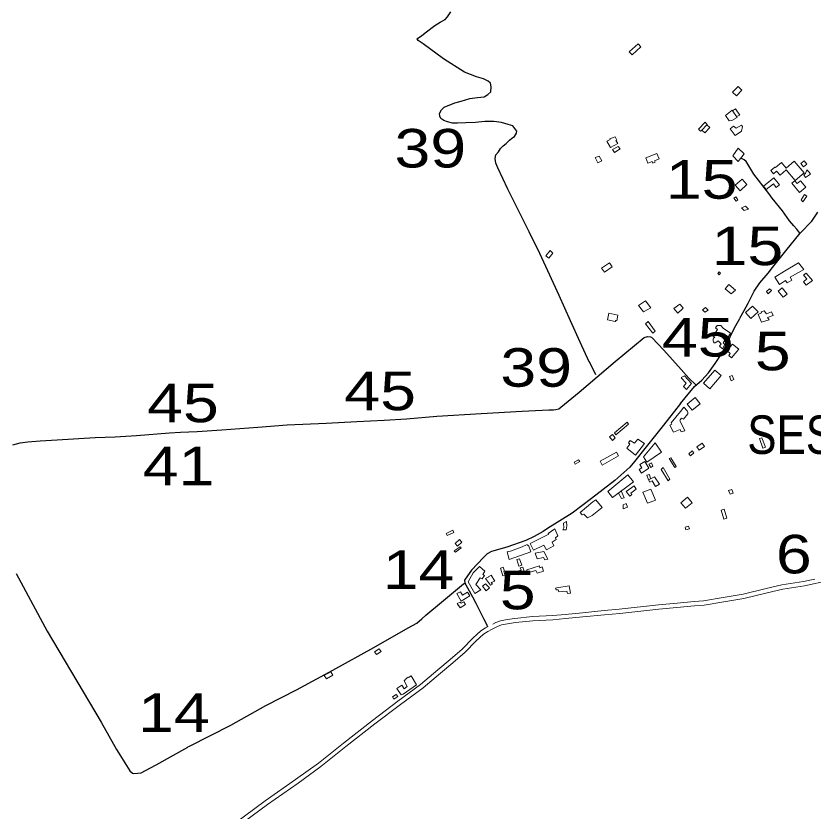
# Model space of a CAD drawing. Extents: x 476989 to 498418, y 4381813 to 4416555.
# Drawn here: x 484565 to 485599, y 4384627 to 4385658 of the extents above; entities that cross this region are included whole.
import ezdxf
from ezdxf.enums import TextEntityAlignment as Align

# ---------------------------------------------------------------- set-up
doc = ezdxf.new("R2010")
doc.units = 0
doc.header["$LTSCALE"] = 20
doc.linetypes.add('MEDIUM_DASHED', pattern=[4.5, 3, -1.5])
for name, color, linetype, lineweight in [('13', 7, 'Continuous', 13), ('36', 7, 'Continuous', 13), ('47', 7, 'Continuous', 13), ('48', 7, 'MEDIUM_DASHED', 13), ('6', 7, 'Continuous', 25)]:
    doc.layers.add(name, color=color, linetype=linetype, lineweight=lineweight)
doc.layers.add('7', color=7, linetype='Continuous')

msp = doc.modelspace()

# ---------------------------------------------------------------- linework, layer by layer
at = {"layer": '36'}
for points in [[(485422.69, 4384896.4), (485445.04, 4384898.28), (485457.06, 4384899.22), (485464.89, 4384900.34), (485474.69, 4384902.21), (485508.34, 4384907.79), (485538.44, 4384915.04), (485558.81, 4384919.82), (485586.93, 4384924.38), (485601.44, 4384927.38)], [(485422.62, 4384890.78), (485445.5, 4384892.7), (485457.67, 4384893.65), (485465.81, 4384894.8), (485475.68, 4384896.69), (485509.45, 4384902.29), (485539.74, 4384909.58), (485559.9, 4384914.32), (485587.94, 4384918.87), (485619.65, 4384925.47)], [(485183.89, 4384869.09), (485187.49, 4384870.96), (485193.57, 4384873.46), (485202.11, 4384874.97), (485212.4, 4384876.37), (485235.13, 4384878.7), (485261.36, 4384880.1), (485277.67, 4384881.57), (485300.11, 4384883.76), (485328.15, 4384886.54), (485347.71, 4384888.4), (485398.68, 4384894.02), (485422.69, 4384896.4)], [(484851.61, 4384605.75), (484891.48, 4384635.27), (484931.04, 4384662.95), (484960.7, 4384684.23), (484993.21, 4384710.28), (485030.75, 4384739.64), (485063.92, 4384764.85), (485093.47, 4384786.49), (485116.03, 4384805.54), (485131.93, 4384818.81), (485147.77, 4384832.69), (485161.73, 4384847.04), (485171.53, 4384855.86), (485177.07, 4384859.62), (485182.06, 4384861.97), (485189.79, 4384866.01), (485195.1, 4384868.19), (485202.95, 4384869.58), (485213.04, 4384870.95), (485235.55, 4384873.26), (485261.75, 4384874.66), (485278.18, 4384876.14), (485300.64, 4384878.33), (485328.67, 4384881.11), (485348.27, 4384882.97), (485399.25, 4384888.59), (485422.62, 4384890.78)], [(484707.31, 4384502.21), (484734.52, 4384522.99), (484765.58, 4384547.94), (484791.08, 4384567.66), (484812.71, 4384583.16), (484848.35, 4384610.12), (484888.3, 4384639.7), (484927.89, 4384667.41), (484957.41, 4384688.58), (484989.83, 4384714.56), (485027.43, 4384743.96), (485060.66, 4384769.23), (485090.09, 4384790.79), (485112.52, 4384809.73), (485128.38, 4384822.96), (485144.01, 4384836.66), (485157.94, 4384850.98), (485168.16, 4384860.16), (485174.35, 4384864.37), (485176.85, 4384865.55)]]:
    msp.add_lwpolyline(points, dxfattribs=at)
at = {"layer": '47'}
for p, q in [((485429.64, 4385279.89), (485430.73, 4385278.66)), ((485430.73, 4385278.66), (485429.6, 4385277.65)), ((485431.59, 4385150.48), (485427.01, 4385144.68))]:
    msp.add_line(p, q, dxfattribs=at)
for points in [[(485375.86, 4385617.36), (485364.42, 4385607.2), (485360.77, 4385611.28), (485372.16, 4385621.45)], [(485501.94, 4385566.31), (485494.71, 4385558.99), (485499.66, 4385554.11), (485506.89, 4385561.43)], [(485500.76, 4385525.8), (485493.57, 4385522.16), (485490.11, 4385521.53), (485485.71, 4385528.5), (485494.07, 4385535.43)], [(485461.45, 4385516.54), (485454.91, 4385509.66), (485458.68, 4385506.07), (485465.22, 4385512.95)], [(485491.39, 4385511.08), (485498.17, 4385502.8), (485506.43, 4385508.01), (485507.49, 4385514.15), (485506.17, 4385515.97), (485499.43, 4385512.02), (485496.02, 4385514.62)], [(485336.5, 4385486.96), (485331.77, 4385495.38), (485335.76, 4385497.44), (485335.29, 4385498.25), (485342.2, 4385500.73), (485344.58, 4385496.66), (485343.21, 4385496.15), (485345.76, 4385492.09)], [(485346.38, 4385488.49), (485348.86, 4385485.12), (485341.52, 4385480.52), (485338.96, 4385484.25)], [(485501.99, 4385486.17), (485494.94, 4385476.06), (485501.89, 4385468.84), (485509.91, 4385478.63)], [(485316.66, 4385474.25), (485319.79, 4385467.3), (485324.91, 4385469.72), (485321.65, 4385475.92)], [(485382.2, 4385473.84), (485385, 4385466.76), (485390.55, 4385468.79), (485391.34, 4385466.68), (485394.27, 4385468.09), (485393.65, 4385469.76), (485399.3, 4385472.35), (485396.43, 4385479.26)], [(485576.12, 4385444.28), (485564.24, 4385457.89), (485556.57, 4385451.2), (485551.89, 4385456.56), (485547.94, 4385453.11), (485544.46, 4385457.09), (485549.66, 4385461.64), (485550.29, 4385460.91), (485558.02, 4385467.59), (485564.31, 4385460.3), (485574.72, 4385469.29), (485587.69, 4385454.27)], [(485583.19, 4385466.47), (485586.58, 4385462.08), (485591.06, 4385465.53), (485587.67, 4385469.92)], [(485591.25, 4385458.17), (485589.16, 4385453.18), (485586.96, 4385451.48), (485589.53, 4385448.14), (485595.75, 4385452.26), (485594.06, 4385455.21)], [(485513.39, 4385438.88), (485504.37, 4385430.87), (485498, 4385438.05), (485507.02, 4385446.06)], [(485534.82, 4385436.85), (485548.41, 4385447.53), (485555.55, 4385438.42), (485551.49, 4385435.24), (485547.76, 4385439.99), (485538.35, 4385432.6)], [(485571.57, 4385440.75), (485581.68, 4385428.75), (485589.75, 4385435.55), (485582.63, 4385443.99), (485578.45, 4385440.47), (485575.5, 4385443.96)], [(485488.51, 4385430.38), (485490.9, 4385426.94), (485494.12, 4385429.18), (485491.73, 4385432.62)], [(485587.94, 4385426.11), (485583.51, 4385419.27), (485585.96, 4385416.4), (485590.99, 4385424.11)], [(485496.41, 4385421.49), (485499.18, 4385417.58), (485501.63, 4385419.31), (485498.86, 4385423.22)], [(485515.18, 4385406.96), (485509.98, 4385405.16), (485506.28, 4385408.67), (485511.49, 4385410.99)], [(485261.75, 4385350.07), (485256.55, 4385343.42), (485252.49, 4385346.53), (485257.99, 4385353.63)], [(485328.63, 4385325.22), (485324.86, 4385330.61), (485335.14, 4385337.31), (485338.56, 4385332.44)], [(485549.71, 4385318.83), (485561.98, 4385326.75), (485580.37, 4385337.6), (485587.23, 4385328.94), (485569.52, 4385318.84), (485571.72, 4385315.06), (485565.44, 4385311.55), (485563.46, 4385314.43), (485555.65, 4385309.29)], [(485477.4, 4385325.79), (485479.27, 4385324.15), (485477.42, 4385322.04), (485475.55, 4385323.68)], [(485590.08, 4385308.34), (485598.5, 4385314.38), (485590.16, 4385324.25), (485586.82, 4385321.45), (485590.88, 4385316.59), (485586.69, 4385312.74)], [(485498.45, 4385302.23), (485490, 4385309.55), (485485.17, 4385303.97), (485492.83, 4385297.33)], [(485542.75, 4385303.99), (485538.6, 4385300.17), (485540.85, 4385297.49), (485545.11, 4385301.63)], [(485559.04, 4385304.89), (485565.52, 4385297.05), (485560.45, 4385292.86), (485553.97, 4385300.7)], [(485379.07, 4385273.78), (485372.7, 4385282.19), (485381.81, 4385288.09), (485388.5, 4385279.35)], [(485462.96, 4385275.95), (485458.57, 4385273.46), (485455.91, 4385276.72), (485459.56, 4385279.6)], [(485520.66, 4385281.5), (485511.38, 4385272.95), (485518.48, 4385265.25), (485527.76, 4385273.8)], [(485345.88, 4385269.62), (485344.44, 4385262.34), (485343.13, 4385262.81), (485342.47, 4385261.32), (485332.59, 4385263.42), (485334.26, 4385272.11)], [(485535.88, 4385275.28), (485538.53, 4385271.26), (485545.24, 4385273.79), (485547.35, 4385269.41), (485540.18, 4385266.44), (485542.09, 4385263.63), (485532.37, 4385260.7), (485528.09, 4385270.51), (485532.09, 4385272.56), (485531.74, 4385273.91)], [(485385.42, 4385261.39), (485394.28, 4385248.91), (485391.08, 4385246.45), (485381.82, 4385258.29)], [(485491.87, 4385246.19), (485482.36, 4385252.63), (485479.41, 4385256.13), (485474.53, 4385256.42), (485472.69, 4385253.22), (485475.36, 4385251.23), (485469.68, 4385242.53), (485471.61, 4385240.93), (485470.02, 4385239.75), (485469.7, 4385238.63), (485469.68, 4385237.51), (485469.66, 4385235.93), (485469.95, 4385235.1), (485470.91, 4385233.81), (485472.33, 4385233.94), (485474.23, 4385235.19), (485476.05, 4385236.29), (485479.89, 4385232.48), (485477.67, 4385229.44), (485481.67, 4385225.85), (485484.68, 4385231.74), (485482.54, 4385233.72), (485485.91, 4385239.08), (485487.71, 4385238.75)], [(485502.9, 4385225.4), (485493.14, 4385214.36), (485489.67, 4385217.42), (485491.81, 4385219.85), (485487.35, 4385223.77), (485494.77, 4385232.21)], [(485471.75, 4385198.38), (485457.07, 4385181.29), (485465.18, 4385174.32), (485479.86, 4385191.41)], [(485494.31, 4385191.46), (485496.54, 4385186.14), (485492.79, 4385184.57), (485490.56, 4385189.89)], [(485446.33, 4385162.95), (485435.67, 4385154.43), (485442.19, 4385146.28), (485452.85, 4385154.8)], [(485341.54, 4385117.13), (485358, 4385131.01), (485359.88, 4385128.25), (485343.44, 4385114.36)], [(485335.12, 4385111.93), (485338.88, 4385107.2), (485342.55, 4385110.64), (485339.07, 4385115.06)], [(485357.51, 4385097.15), (485368.62, 4385088.17), (485380.36, 4385103.26), (485372.01, 4385109.03), (485367.56, 4385103.58), (485362.09, 4385107.01), (485359.66, 4385104.07), (485361.62, 4385102.4)], [(485379.23, 4385085.92), (485383.64, 4385079.14), (485402.54, 4385092.1), (485394.26, 4385104.11)], [(485458.4, 4385099.53), (485451.27, 4385094.65), (485448.34, 4385098.92), (485455.47, 4385103.8)], [(485532.7, 4385110.77), (485537.34, 4385098.3), (485534.08, 4385097.09), (485529.44, 4385109.56)], [(485444.62, 4385090.94), (485440.26, 4385087.1), (485437.78, 4385089.92), (485442.14, 4385093.76)], [(485346.7, 4385087.36), (485344.04, 4385092.2), (485323.12, 4385080.13), (485325.71, 4385075.16)], [(485414.69, 4385084.77), (485421.67, 4385073.34), (485420.02, 4385071.95), (485412.62, 4385083.7)], [(485290.74, 4385076.25), (485296.71, 4385079.76), (485295.04, 4385081.98), (485289.22, 4385078.94)], [(485376.42, 4385064.78), (485386.3, 4385071.05), (485380.99, 4385079.78), (485374.59, 4385076.18), (485377.22, 4385071.74), (485373.36, 4385069.71)], [(485386.27, 4385076.22), (485388.49, 4385071.93), (485391.18, 4385073.68), (485389.36, 4385078.3)], [(485401.88, 4385069.6), (485410.97, 4385054.66), (485413.3, 4385056.85), (485404.78, 4385072.14)], [(485332.83, 4385040.86), (485358.81, 4385062.46), (485366.1, 4385053.67), (485338.95, 4385033.1)], [(485400.09, 4385050.6), (485393.57, 4385059.83), (485385.55, 4385056.3), (485387.34, 4385053.1), (485390.5, 4385054.62), (485394.78, 4385047.66)], [(485356.66, 4385040.89), (485366.9, 4385048.44), (485369.63, 4385044), (485362.81, 4385039.04), (485363.91, 4385036.96), (485361.23, 4385035.02)], [(485378.19, 4385039.92), (485388.72, 4385044.18), (485394.8, 4385029.82), (485384.25, 4385025.7)], [(485489.62, 4385042.13), (485493.73, 4385043.77), (485495.65, 4385038.96), (485491.54, 4385037.32)], [(485436.15, 4385033.44), (485427.79, 4385026.2), (485433.84, 4385019.21), (485442.2, 4385026.45)], [(485317.22, 4385029.98), (485325.37, 4385020.45), (485312.51, 4385010.01), (485306.62, 4385006.83), (485301.81, 4385011.58), (485299.61, 4385010.55), (485296.92, 4385013.86), (485313.3, 4385027.75)], [(485356.54, 4385025.58), (485358.36, 4385020.59), (485352.67, 4385018.3), (485352.65, 4385023.86)], [(485483.95, 4385017.97), (485487.31, 4385006.49), (485483.24, 4385005.3), (485479.88, 4385016.78)], [(485275.35, 4384999.72), (485275.62, 4384993.72), (485274.51, 4384991.12), (485278.93, 4384991.49), (485279.63, 4384996.44), (485279.21, 4385002.07)], [(485131.88, 4384990.73), (485133.04, 4384987.96), (485124.38, 4384983.93), (485123.04, 4384986.67)], [(485232.24, 4384973.73), (485256.24, 4384985.71), (485255.64, 4384986.42), (485264.26, 4384992.64), (485267.98, 4384983.55), (485264.85, 4384980.92), (485265.96, 4384978.66), (485260.82, 4384975.22), (485262.98, 4384970.42), (485253.45, 4384965.37), (485249.92, 4384971.55), (485236.63, 4384965.07)], [(485434.27, 4384991.29), (485438.67, 4384992.73), (485437.56, 4384996.12), (485433.16, 4384994.68)], [(485135.13, 4384962.27), (485133.6, 4384964.2), (485141.49, 4384969.44), (485142.72, 4384967.81)], [(485134.96, 4384973.48), (485137.8, 4384970.26), (485143.62, 4384975.18), (485140.65, 4384978.64)], [(485202.26, 4384962.64), (485205.11, 4384952.88), (485232.87, 4384962.57), (485229.87, 4384971.23), (485228.85, 4384971.04), (485228.23, 4384972.06), (485221.76, 4384969.24), (485206.44, 4384963.71)], [(485241.19, 4384953.59), (485238.74, 4384961.16), (485249.91, 4384963.4), (485255.04, 4384953.22), (485251.01, 4384952.26), (485249.57, 4384955.39)], [(485218.26, 4384953.88), (485221.3, 4384945.37), (485217.52, 4384944.38), (485214.88, 4384952.63)], [(485166.54, 4384943.66), (485173.38, 4384937.5), (485170.74, 4384933.52), (485172.96, 4384932.16), (485170.02, 4384927.89), (485167.44, 4384928.93), (485161.73, 4384920.25), (485168.12, 4384913.52), (485160.35, 4384908.85), (485151.84, 4384923.7), (485158.04, 4384935.36)], [(485196.83, 4384931.59), (485193.55, 4384941.49), (485197.01, 4384942.93), (485198.74, 4384937.86), (485198.11, 4384937.64), (485199.61, 4384932.22)], [(485222.65, 4384942.91), (485225.26, 4384935.23), (485216.88, 4384932.94), (485215.88, 4384937.84), (485220.3, 4384938.94), (485219.08, 4384941.85)], [(485249.49, 4384937.5), (485241.12, 4384935.21), (485239.52, 4384938.69), (485228.76, 4384935.35), (485227.77, 4384939.36), (485244.05, 4384944.48), (485244.89, 4384942.19), (485247.54, 4384943.11)], [(485186.49, 4384924.62), (485181.37, 4384932.42), (485178.47, 4384930.93), (485178.71, 4384930.27), (485174.01, 4384928), (485180.62, 4384919.36), (485183.12, 4384920.9), (485181.75, 4384922.86)], [(485174.13, 4384921.38), (485179.41, 4384916.01), (485175.21, 4384912.35), (485170.29, 4384918.41)], [(485266.7, 4384916.2), (485282.71, 4384918.56), (485284.62, 4384909.24), (485280.59, 4384908.66), (485279.6, 4384911.79), (485269.14, 4384910.81), (485268.41, 4384913.55), (485265.87, 4384913.33), (485264.93, 4384915.83)], [(485142.63, 4384898.78), (485154.08, 4384905.6), (485151.02, 4384910.61), (485144.58, 4384906.61), (485141.69, 4384910.99), (485137.02, 4384908.61)], [(485137.57, 4384895.7), (485141.36, 4384889.94), (485148.18, 4384894.62), (485146.28, 4384897.8), (485142.69, 4384896.02), (485141.37, 4384897.6)], [(485038.74, 4384833.32), (485032.85, 4384829.56), (485030.27, 4384833.1), (485036.4, 4384836.94)], [(484964.87, 4384802.3), (484967.76, 4384797.99), (484976.23, 4384802.68), (484973.49, 4384807.16)], [(485077.7, 4384801.78), (485084.8, 4384790.17), (485067.22, 4384778.07), (485064.7, 4384777.53), (485059.16, 4384785.44), (485065.69, 4384789.96), (485068.86, 4384784.97), (485072.67, 4384788.24), (485068.78, 4384795.47), (485070.08, 4384796.6), (485069.91, 4384797.28), (485073.98, 4384800.36), (485074.47, 4384799.7)], [(485058.21, 4384777.93), (485060.61, 4384775.18), (485055.1, 4384771.73), (485053.37, 4384774.59)]]:
    msp.add_lwpolyline(points, close=True, dxfattribs=at)
for points in [[(485429.64, 4385279.89), (485426.15, 4385283.84), (485418.4, 4385278.2), (485423.65, 4385272.41), (485429.6, 4385277.65)], [(485427.86, 4385188.7), (485432.25, 4385191), (485441.64, 4385181.18)], [(485441.64, 4385181.18), (485434.85, 4385173.17), (485431, 4385177.06), (485434.44, 4385181.58), (485427.86, 4385188.36)], [(485427.01, 4385144.68), (485414.85, 4385130.05), (485416.09, 4385128.19), (485413.43, 4385126.89), (485418.24, 4385117.89), (485426.55, 4385121.28)], [(485426.79, 4385133.81), (485428.39, 4385136.27), (485430.92, 4385134.66), (485436.72, 4385141.78), (485436.75, 4385143.51), (485435.88, 4385145.77), (485431.59, 4385150.48)], [(485426.76, 4385132.14), (485426.34, 4385133.12), (485426.79, 4385133.81)], [(485426.55, 4385121.28), (485428.06, 4385118.42), (485432.65, 4385119.55), (485426.76, 4385132.14)], [(485385.55, 4385056.3), (485383.4, 4385062.17), (485386.75, 4385063.22), (485388.34, 4385057.54)], [(485350.4, 4385041.78), (485353.89, 4385032.82), (485350.82, 4385031.71), (485346.73, 4385039)]]:
    msp.add_lwpolyline(points, dxfattribs=at)
at = {"layer": '48'}
for points in [[(485494.62, 4385534.65), (485498.59, 4385537.17), (485504.3, 4385529.07), (485499.88, 4385527.08)], [(485462.03, 4385516), (485459.32, 4385519.8), (485450.49, 4385510.99), (485453.01, 4385508.33), (485455.17, 4385509.42)]]:
    msp.add_lwpolyline(points, dxfattribs=at)
at = {"layer": '6'}
msp.add_line((485317.14, 4385192.15), (485308.96, 4385209), dxfattribs=at)
for points in [[(485085.26, 4385628.04), (485091.15, 4385632.01), (485096.05, 4385635.71), (485108.29, 4385645.35), (485115.31, 4385649.61), (485121.88, 4385653.16), (485124.79, 4385656.54), (485129.25, 4385663.08)], [(485308.74, 4385209.32), (485296.92, 4385234.62), (485284.43, 4385262.28), (485269.87, 4385294.93), (485255.01, 4385327.15), (485244.49, 4385349.47), (485230.92, 4385377.71), (485215.65, 4385407.92), (485203.16, 4385433.2), (485190.33, 4385460.5), (485187.63, 4385466.91), (485186.62, 4385472.64), (485187.63, 4385477.36), (485190.89, 4385481.57), (485193.57, 4385485.92), (485197.06, 4385489.39), (485200.8, 4385492.38), (485205.32, 4385496.6), (485208.41, 4385498.94), (485211.95, 4385501.28), (485214.31, 4385505.63), (485214.74, 4385508.31), (485209.48, 4385515.04), (485203.51, 4385516.95), (485195.07, 4385519.6), (485184.8, 4385520.86), (485173.16, 4385520.87), (485161.39, 4385519.61), (485148.88, 4385519.03), (485137.95, 4385518.42), (485131.25, 4385518.7), (485124.8, 4385520.19), (485120.08, 4385522.1), (485116.29, 4385524.57), (485114.78, 4385527.83), (485114.56, 4385531.16), (485116.92, 4385535.98), (485120.69, 4385539.39), (485134.43, 4385544.79), (485142.84, 4385547.22), (485153.81, 4385550.55), (485163.77, 4385551.71), (485172.59, 4385552.94), (485177.26, 4385555.7), (485181.21, 4385559.31), (485181.69, 4385565.62), (485180.62, 4385570.61), (485177.49, 4385573.08), (485171.64, 4385576.01), (485162.45, 4385578.88), (485146.78, 4385584.79), (485119.71, 4385602.02), (485093.36, 4385621.51), (485087.04, 4385625.83), (485085.38, 4385628.14)], [(485582.1, 4385375.98), (485578.17, 4385381.31), (485574, 4385385.61), (485568.72, 4385391.95), (485559.52, 4385404.75), (485546.16, 4385421.17), (485541.55, 4385427.29), (485522.24, 4385452.62), (485513.26, 4385467.74), (485512.2, 4385468.93), (485509.6, 4385470.94), (485505.65, 4385473.38)], [(485504.14, 4385265.76), (485509.89, 4385275.82), (485514.92, 4385285.15), (485522.59, 4385300.57), (485530.19, 4385311.59), (485540.73, 4385324.04), (485546.48, 4385331.36), (485563.74, 4385352.91), (485582.43, 4385376.13), (485597.52, 4385391.7), (485605.43, 4385403.19)], [(485427.21, 4385155.18), (485445.15, 4385177.06), (485454.85, 4385185.2), (485463.48, 4385194.77), (485472.34, 4385206.98), (485479.05, 4385217.52), (485485.93, 4385229.85), (485497.43, 4385253.31), (485504.14, 4385265.28)], [(484721.33, 4385113.65), (484764.31, 4385117.19), (484778.74, 4385117.71), (484800.28, 4385118.92), (484831.98, 4385121), (484878.85, 4385124.3), (484916.93, 4385127.45), (484967.4, 4385129.79), (485007.23, 4385131.89), (485042.9, 4385133.62), (485071.57, 4385135.19), (485111.25, 4385138.74), (485168.74, 4385142.21), (485221.87, 4385145.3), (485256.19, 4385146.79), (485262.58, 4385146.84), (485265.43, 4385147.4), (485269.18, 4385148.39), (485271.82, 4385150.33), (485295.88, 4385169.82), (485342.32, 4385209.37), (485380.09, 4385240.53), (485384.25, 4385242.18), (485388.13, 4385241.7), (485389.63, 4385241.04), (485389.91, 4385240.71), (485405.62, 4385224.4), (485428.07, 4385199.13)], [(485447.21, 4385179.34), (485437.95, 4385187.81), (485428.09, 4385199.1), (485428.07, 4385199.13)], [(485427.21, 4385155.18), (485405.21, 4385126.89), (485382.59, 4385098.77), (485367.56, 4385079.71), (485361.63, 4385072.41), (485341.83, 4385055.04), (485311.5, 4385032.01), (485286.65, 4385012.95), (485254.81, 4384992.98), (485249.03, 4384989.33), (485237.16, 4384982.81), (485226.33, 4384977.63), (485202.03, 4384968.94), (485181.81, 4384963.08), (485176.45, 4384960.11), (485171.5, 4384955.6), (485155.92, 4384938.89), (485147.88, 4384927.31), (485147.13, 4384926), (485147.27, 4384922.29), (485148.81, 4384919.8), (485155.15, 4384908.42), (485157.31, 4384904.48), (485161.8, 4384896.09), (485168.3, 4384883.05), (485171.89, 4384875.57), (485174.86, 4384870), (485176.85, 4384865.55)], [(484560.92, 4385101.66), (484570.5, 4385104.22), (484580.6, 4385105.21), (484596.61, 4385106.51), (484618.44, 4385108.14), (484667.62, 4385110.91), (484693.66, 4385111.99), (484721.33, 4385113.65)], [(484565.32, 4384934.84), (484605.7, 4384860.08), (484675.78, 4384741.99), (484695.63, 4384706.66), (484712.65, 4384678.75), (484716.37, 4384675.91), (484718.11, 4384675.18), (484727.45, 4384676.03), (484733.24, 4384679.19), (484746.86, 4384686.49), (484788.02, 4384709.66)], [(484788.22, 4384709.74), (484790.05, 4384710.77), (484843.73, 4384738.03), (484889.45, 4384763.36), (484928.92, 4384783.99), (484975.95, 4384809.37), (485029.5, 4384838.87), (485074.04, 4384864.28), (485084.96, 4384870.3), (485091.46, 4384875.82), (485096.64, 4384880.61), (485117.13, 4384897.31), (485145.79, 4384921.2), (485147.48, 4384921.96)]]:
    msp.add_lwpolyline(points, dxfattribs=at)

# ---------------------------------------------------------------- texts
at = {"layer": '13', "width": 1.25}
for s, p in [('39', (485102.6, 4385461.1)), ('15', (485454.61, 4385420.63)), ('15', (485514.01, 4385334.51)), ('45', (485449.56, 4385216)), ('5', (485546.77, 4385198.14)), ('39', (485239.97, 4385176.84)), ('45', (485037.56, 4385146.41)), ('45', (484781.71, 4385130.81)), ('41', (484775.97, 4385049.16)), ('6', (485574.19, 4384934.8)), ('14', (485087.35, 4384914.55)), ('5', (485215.97, 4384888.23)), ('14', (484770.01, 4384729.3))]:
    msp.add_text(s, height=50, dxfattribs=at).set_placement(p, align=Align.CENTER)
at = {"layer": '7', "width": 0.85}
msp.add_text('SES OLLERIES', height=50, dxfattribs=at).set_placement((485717.6, 4385089.66), align=Align.CENTER)

doc.saveas('drawing.dxf')
